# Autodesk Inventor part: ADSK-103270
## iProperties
Created: 2000-09
Part Number: ADSK-103270
Description: Hexagon Socket Head Cap Screw
Document SubType Name: Modeling
Standard: ANSI B18.3 - No. 10 - 24 - 1 3/8
Density: 1 g/cm^3
Control State: 0
Master: False
Checked Out: False
Shininess: 0.0
Density: 0.0
Volumn: 0.0
Area: 0.0
PropertySet Name: Model Information
Author: Administrator
